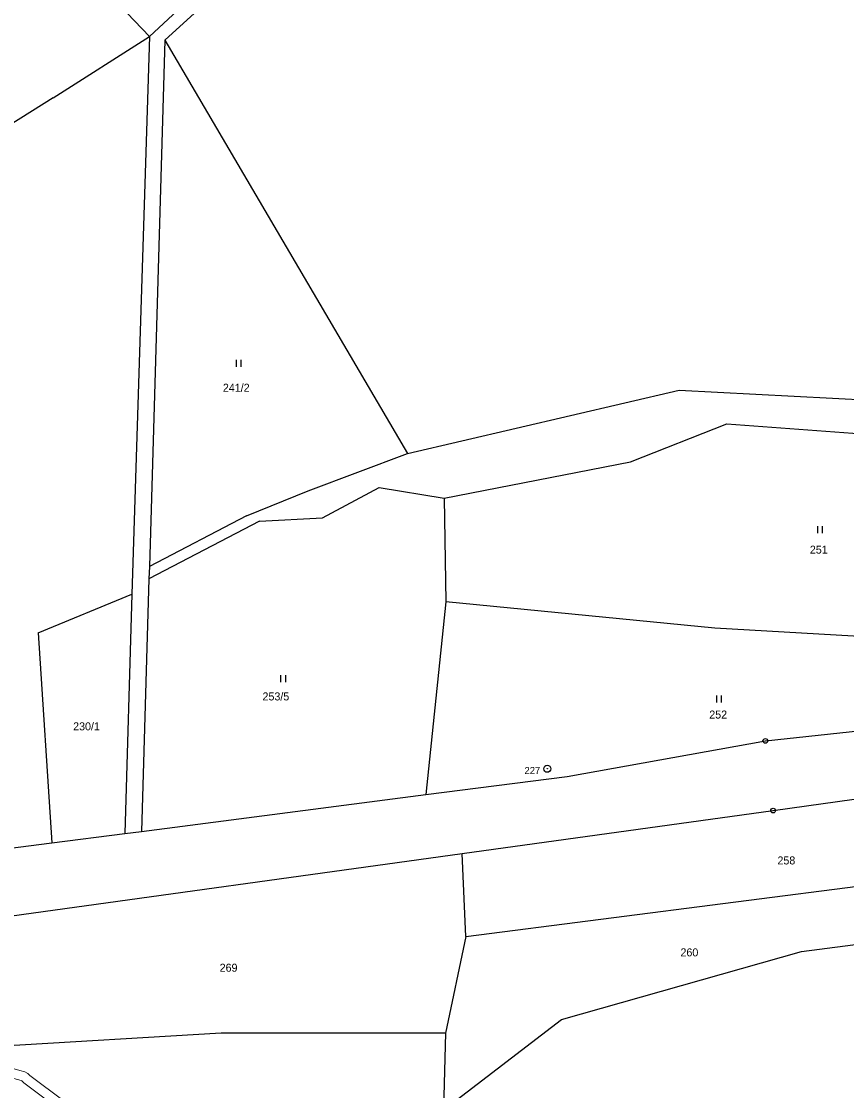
# Model space of a CAD drawing. Extents: x -664548 to -662415, y -1069720 to -1068208.
# Drawn here: x -662907.1 to -662731.7, y -1068901.8 to -1068674.7 of the extents above; entities that cross this region are included whole.
import ezdxf
from ezdxf.enums import TextEntityAlignment as Align

# ---------------------------------------------------------------- set-up
doc = ezdxf.new("R2010")
doc.units = 0
doc.header["$LTSCALE"] = 0.68
for name, color, linetype, lineweight in [('1', 7, 'Continuous', 25), ('13', 7, 'Continuous', 13), ('3', 7, 'Continuous', 25), ('8', 7, 'Continuous', 25)]:
    doc.layers.add(name, color=color, linetype=linetype, lineweight=lineweight)
doc.layers.add('2', color=7, linetype='Continuous')

msp = doc.modelspace()

# ---------------------------------------------------------------- linework, layer by layer
at = {"layer": '1'}
for p, q in [((-662848.55, -1068648.75), (-662879.87, -1068677.92)), ((-662895.01, -1068662.05), (-662879.87, -1068677.92)), ((-662900.34, -1068690.96), (-662879.87, -1068677.92)), ((-662879.87, -1068677.92), (-662883.67, -1068796.4)), ((-662876.64, -1068678.68), (-662879.92, -1068790.54)), ((-662900.34, -1068690.96), (-662966.49, -1068732.18)), ((-662825.07, -1068766.52), (-662767.34, -1068753.04)), ((-662767.34, -1068753.04), (-662696.77, -1068756.73)), ((-662777.66, -1068768.3), (-662757.21, -1068760.23)), ((-662757.21, -1068760.23), (-662661.48, -1068767.3)), ((-662846.16, -1068774.42), (-662825.07, -1068766.52)), ((-662817.26, -1068776.01), (-662777.66, -1068768.3)), ((-662859.26, -1068779.79), (-662846.16, -1068774.42)), ((-662843.1, -1068780.18), (-662831.08, -1068773.73)), ((-662831.08, -1068773.73), (-662817.26, -1068776.01)), ((-662817.26, -1068776.01), (-662816.93, -1068797.99)), ((-662859.26, -1068779.79), (-662879.92, -1068790.54)), ((-662856.54, -1068780.91), (-662880, -1068793.12)), ((-662856.54, -1068780.91), (-662843.1, -1068780.18)), ((-662879.92, -1068790.54), (-662880, -1068793.12)), ((-662880, -1068793.12), (-662881.57, -1068846.78)), ((-662903.57, -1068804.61), (-662883.67, -1068796.4)), ((-662883.67, -1068796.4), (-662885.16, -1068847.24)), ((-662816.93, -1068797.99), (-662821.13, -1068838.98)), ((-662759.72, -1068803.63), (-662816.93, -1068797.99)), ((-662903.57, -1068804.61), (-662900.68, -1068849.24)), ((-662678.69, -1068808.31), (-662759.72, -1068803.63)), ((-662748.99, -1068827.56), (-662719.29, -1068824.31)), ((-662791.11, -1068835.11), (-662748.99, -1068827.56)), ((-662747.34, -1068842.37), (-662680.05, -1068832.95)), ((-662821.13, -1068838.98), (-662791.11, -1068835.11)), ((-662881.57, -1068846.78), (-662821.13, -1068838.98)), ((-662813.46, -1068851.51), (-662747.34, -1068842.37)), ((-662900.68, -1068849.24), (-662885.16, -1068847.24)), ((-662885.16, -1068847.24), (-662881.57, -1068846.78)), ((-662962.55, -1068857.22), (-662900.68, -1068849.24)), ((-662911.77, -1068865.09), (-662813.46, -1068851.51)), ((-662812.62, -1068869.13), (-662813.46, -1068851.51)), ((-662812.62, -1068869.13), (-662703.91, -1068855.19)), ((-662741.29, -1068872.27), (-662700.26, -1068866.98)), ((-662812.62, -1068869.13), (-662816.96, -1068889.63)), ((-662792.31, -1068886.74), (-662741.29, -1068872.27)), ((-662816.62, -1068905.4), (-662792.31, -1068886.74)), ((-662864.66, -1068889.63), (-662917.67, -1068892.82)), ((-662816.96, -1068889.63), (-662864.66, -1068889.63)), ((-662816.96, -1068889.63), (-662817.37, -1068905.73))]:
    msp.add_line(p, q, dxfattribs=at)
msp.add_lwpolyline([(-662846.14, -1068650.99), (-662876.64, -1068678.68), (-662825.07, -1068766.52)], dxfattribs=at)
at = {"layer": '13'}
msp.add_lwpolyline([(-662907.96, -1068899.47), (-662907.16, -1068899.69), (-662907.02, -1068899.77), (-662906.63, -1068900.17), (-662892.2, -1068910.96), (-662877.92, -1068921.76), (-662874.66, -1068921.73), (-662875.31, -1068921.23), (-662891, -1068909.36), (-662905.31, -1068898.65), (-662905.78, -1068898.19), (-662906.36, -1068897.83), (-662907.44, -1068897.55), (-662918.17, -1068894.51), (-662918.75, -1068896.42)], close=True, dxfattribs=at)
at = {"layer": '3'}
for p, q in [((-662861.381, -1068748.1), (-662861.381, -1068746.6)), ((-662860.38, -1068748.1), (-662860.38, -1068746.6)), ((-662737.861, -1068783.46), (-662737.861, -1068781.96)), ((-662736.86, -1068783.46), (-662736.86, -1068781.96)), ((-662851.941, -1068815.11), (-662851.941, -1068813.61)), ((-662850.94, -1068815.11), (-662850.94, -1068813.61)), ((-662759.291, -1068819.39), (-662759.291, -1068817.89)), ((-662758.29, -1068819.39), (-662758.29, -1068817.89))]:
    msp.add_line(p, q, dxfattribs=at)
at = {"layer": '8'}
for centre, radius in [((-662748.99, -1068827.5599), 0.5), ((-662748.99, -1068827.5599), 0.0303), ((-662795.34, -1068833.4798), 0.75), ((-662795.34, -1068833.4798), 0.03), ((-662747.34, -1068842.3699), 0.5), ((-662747.34, -1068842.3699), 0.0303)]:
    msp.add_circle(centre, radius, dxfattribs=at)

# ---------------------------------------------------------------- texts
at = {"layer": '2'}
for s, p in [('241/2', (-662864.29, -1068753.395)), ('251', (-662739.53, -1068787.785)), ('253/5', (-662855.87, -1068818.965)), ('252', (-662760.91, -1068822.814)), ('230/1', (-662896.12, -1068825.324)), ('258', (-662746.42, -1068853.804)), ('260', (-662767.03, -1068873.334)), ('269', (-662864.98, -1068876.594))]:
    msp.add_text(s, height=1.7, dxfattribs=at).set_placement(p)
at = {"layer": '8'}
msp.add_text('227', height=1.5, dxfattribs=at).set_placement((-662796.839, -1068834.597), align=Align.RIGHT)

doc.saveas('drawing.dxf')
